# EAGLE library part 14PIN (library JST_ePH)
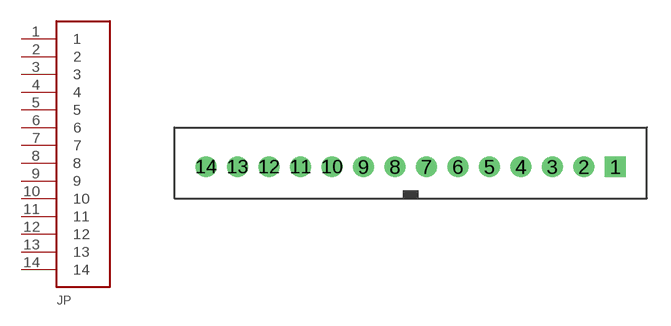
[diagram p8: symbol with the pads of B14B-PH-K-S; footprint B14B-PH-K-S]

Designator prefix JP

## 14PIN  [B14B-PH-K-S]
1  1
2  2
3  3
4  4
5  5
6  6
7  7
8  8
9  9
10  10
11  11
12  12
13  13
14  14

## Footprint B14B-PH-K-S (pad centres in mm)
drill 0.813 square: 1 13,0
drill 0.813 round: 2 11,0; 3 9,0; 4 7,0; 5 5,0; 6 3,0; 7 1,0; 8 -1,0; 9 -3,0; 10 -5,0; 11 -7,0; 12 -9,0; 13 -11,0; 14 -13,0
